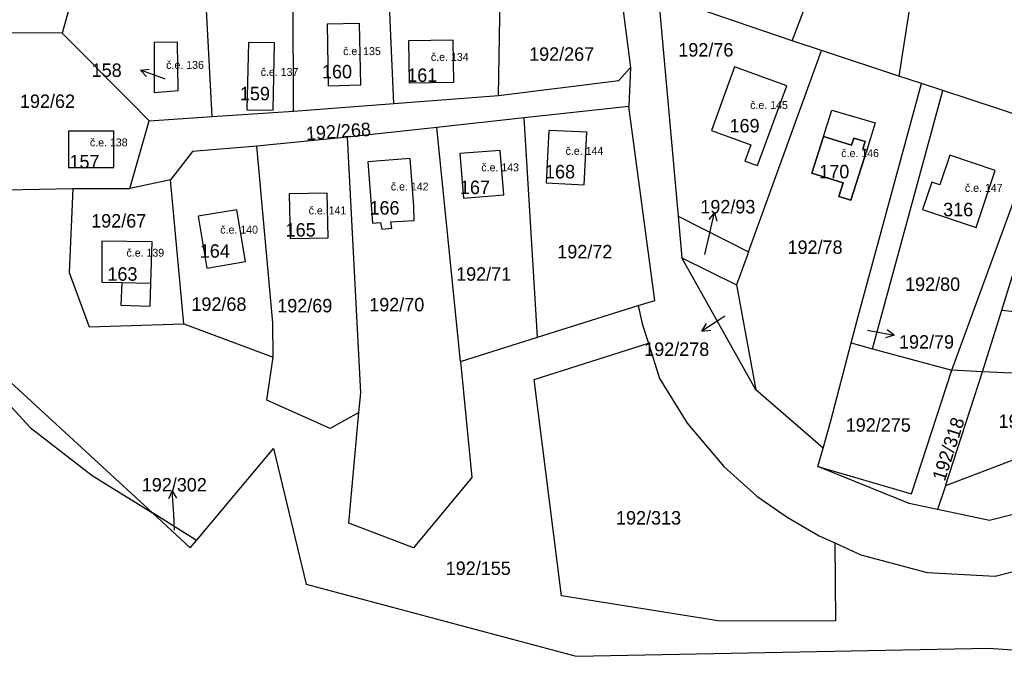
# Model space of a CAD drawing. Extents: x -887272 to -880188, y -1026687 to -1021896.
# Drawn here: x -882457.7 to -882333.3, y -1024320.7 to -1024238.2 of the extents above; entities that cross this region are included whole.
import ezdxf

# ---------------------------------------------------------------- set-up
doc = ezdxf.new("R2010")
doc.units = 0
for name, color, linetype in [('Definiční body', 7, 'Continuous'), ('Hranice parcel', 7, 'Continuous'), ('Parcelní čísla', 7, 'Continuous'), ('Polygon budovy', 7, 'Continuous'), ('Pop  PČ popisy', 7, 'Continuous'), ('Vnitřní kresba', 7, 'Continuous')]:
    doc.layers.add(name, color=color, linetype=linetype)

msp = doc.modelspace()

# ---------------------------------------------------------------- linework, layer by layer
at = {"layer": 'Hranice parcel'}
for p, q in [((-882410.38, -1024248.8), (-882411.4, -1024225.24)), ((-882397.17, -1024247.78), (-882396.78, -1024225.38)), ((-882382.84, -1024225.57), (-882380.49, -1024244.25)), ((-882423.04, -1024249.77), (-882423.15, -1024226.52)), ((-882433.35, -1024250.44), (-882434.56, -1024227.19)), ((-882360.05, -1024240.88), (-882376.96, -1024235.08)), ((-882376.96, -1024235.08), (-882374.46, -1024263.02)), ((-882452.28, -1024239.89), (-882460.64, -1024239.85)), ((-882356.35, -1024242.1), (-882360.05, -1024240.88)), ((-882365.56, -1024267.53), (-882356.35, -1024242.1)), ((-882346.59, -1024245.32), (-882356.35, -1024242.1)), ((-882380.49, -1024244.25), (-882380.71, -1024249.15)), ((-882343.72, -1024246.27), (-882346.59, -1024245.32)), ((-882341.03, -1024247.16), (-882343.72, -1024246.27)), ((-882410.38, -1024248.8), (-882397.17, -1024247.78)), ((-882349.89, -1024279.78), (-882341.03, -1024247.16)), ((-882328.48, -1024251.3), (-882341.03, -1024247.16)), ((-882423.04, -1024249.77), (-882410.38, -1024248.8)), ((-882380.71, -1024249.15), (-882393.92, -1024250.6)), ((-882441.28, -1024250.96), (-882433.35, -1024250.44)), ((-882433.35, -1024250.44), (-882423.04, -1024249.77)), ((-882393.92, -1024250.6), (-882404.93, -1024251.81)), ((-882392.22, -1024278.32), (-882393.92, -1024250.6)), ((-882443.73, -1024259.52), (-882441.28, -1024250.96)), ((-882404.93, -1024251.81), (-882416.23, -1024253.06)), ((-882401.95, -1024281.38), (-882404.93, -1024251.81)), ((-882339.9, -1024282.5), (-882328.48, -1024251.3)), ((-882416.23, -1024253.06), (-882427.71, -1024254.18)), ((-882438.6, -1024258.43), (-882443.73, -1024259.52)), ((-882436.92, -1024276.61), (-882438.6, -1024258.43)), ((-882450.92, -1024259.54), (-882443.73, -1024259.52)), ((-882374.46, -1024263.02), (-882365.56, -1024267.53)), ((-882374.46, -1024263.02), (-882373.99, -1024268.29)), ((-882434.02, -1024269.59), (-882429.14, -1024268.77)), ((-882373.99, -1024268.29), (-882367.08, -1024271.72)), ((-882364.65, -1024284.97), (-882373.99, -1024268.29)), ((-882367.08, -1024271.72), (-882364.65, -1024284.97)), ((-882392.22, -1024278.32), (-882379.5, -1024274.33)), ((-882379.5, -1024274.33), (-882379, -1024276.62)), ((-882335.99, -1024282.71), (-882333.57, -1024274.9)), ((-882333.57, -1024274.9), (-882314.06, -1024277.04)), ((-882436.92, -1024276.61), (-882425.64, -1024280.82)), ((-882379, -1024276.62), (-882378.22, -1024279.09)), ((-882401.95, -1024281.38), (-882392.22, -1024278.32)), ((-882352.62, -1024279.03), (-882349.89, -1024279.78)), ((-882349.89, -1024279.78), (-882339.9, -1024282.5)), ((-882340.7, -1024297.09), (-882335.99, -1024282.71)), ((-882335.99, -1024282.71), (-882339.9, -1024282.5)), ((-882305.94, -1024283.91), (-882335.99, -1024282.71)), ((-882305.94, -1024283.91), (-882340.7, -1024297.09)), ((-882356.14, -1024292.34), (-882364.65, -1024284.97)), ((-882435.31, -1024303.99), (-882425.59, -1024292.38)), ((-882356.8, -1024294.67), (-882356.14, -1024292.34)), ((-882340.7, -1024297.09), (-882341.68, -1024300.07)), ((-882435.31, -1024303.99), (-882440.89, -1024300.52))]:
    msp.add_line(p, q, dxfattribs=at)
for points in [[(-882425.59, -1024292.38), (-882421.44, -1024309.52), (-882387.34, -1024318.62), (-882335.2, -1024317.62), (-882324.6, -1024318.36), (-882301.38, -1024320.66), (-882228.26, -1024295.72), (-882166.04, -1024261.72), (-882132.4, -1024219.02), (-882083.16, -1024195.4)], [(-882346.41, -1024203.09), (-882344.31, -1024230.73), (-882346.59, -1024245.32)], [(-882360.05, -1024240.88), (-882355.97, -1024230.12), (-882356.96, -1024221.54)], [(-882434.56, -1024227.19), (-882450.17, -1024232.3), (-882452.28, -1024239.89)], [(-882440.89, -1024300.52), (-882464.08, -1024279.19), (-882474.4, -1024257.7), (-882487.23, -1024239.16)], [(-882487.23, -1024239.16), (-882478.4, -1024256.44), (-882466.55, -1024277.28), (-882463.36, -1024282.12), (-882456.33, -1024289.73), (-882448.49, -1024295.79), (-882440.89, -1024300.52)], [(-882418.81, -1024238.75), (-882418.66, -1024246.56), (-882414.56, -1024246.42), (-882414.71, -1024238.67), (-882418.81, -1024238.75)], [(-882460.64, -1024239.85), (-882459.44, -1024259.7), (-882450.92, -1024259.54)], [(-882441.28, -1024250.96), (-882443.66, -1024248.58), (-882452.28, -1024239.89)], [(-882408.51, -1024240.88), (-882408.43, -1024246.19), (-882402.82, -1024246.1), (-882402.9, -1024240.79), (-882408.51, -1024240.88)], [(-882440.66, -1024241.1), (-882440.68, -1024247.38), (-882437.62, -1024247.16), (-882437.7, -1024241.02), (-882440.66, -1024241.1)], [(-882428.97, -1024249.57), (-882425.65, -1024249.65), (-882425.44, -1024241.14), (-882428.76, -1024241.06), (-882428.97, -1024249.57)], [(-882397.17, -1024247.78), (-882381.94, -1024245.87), (-882380.49, -1024244.25)], [(-882360.75, -1024246.56), (-882367.33, -1024244.15), (-882370.24, -1024252.19), (-882365.28, -1024254.01), (-882366.02, -1024256.06), (-882364.42, -1024256.61), (-882360.75, -1024246.56)], [(-882352.62, -1024279.03), (-882351.55, -1024275.07), (-882343.72, -1024246.27)], [(-882379.5, -1024274.33), (-882377.41, -1024273.67), (-882380.71, -1024249.15)], [(-882354.14, -1024260.55), (-882353.6, -1024258.83), (-882357.56, -1024257.58), (-882356.1, -1024252.96), (-882355.05, -1024249.64), (-882349.56, -1024251.25), (-882350.64, -1024254.68), (-882352.64, -1024261.02), (-882354.14, -1024260.55)], [(-882451.48, -1024252.28), (-882451.48, -1024256.88), (-882445.78, -1024256.88), (-882445.78, -1024252.28), (-882451.48, -1024252.28)], [(-882414.79, -1024287.85), (-882414.56, -1024285.34), (-882416.23, -1024253.06)], [(-882391.15, -1024258.82), (-882386.34, -1024259.06), (-882386.01, -1024252.42), (-882390.82, -1024252.18), (-882391.15, -1024258.82)], [(-882427.71, -1024254.18), (-882435.8, -1024254.84), (-882438.6, -1024258.43)], [(-882425.64, -1024280.82), (-882425.69, -1024276.49), (-882427.71, -1024254.18)], [(-882396.94, -1024254.71), (-882402.03, -1024255.11), (-882401.59, -1024260.74), (-882396.5, -1024260.34), (-882396.94, -1024254.71)], [(-882336.79, -1024264.46), (-882334.39, -1024257.24), (-882340.13, -1024255.33), (-882341.38, -1024259.08), (-882342.43, -1024258.74), (-882343.58, -1024262.2), (-882336.79, -1024264.46)], [(-882333.57, -1024274.9), (-882328.36, -1024258.07), (-882318.06, -1024254.51)], [(-882411.9, -1024264.66), (-882410.63, -1024264.56), (-882410.75, -1024263.76), (-882407.81, -1024263.55), (-882407.87, -1024261.75), (-882408.3, -1024255.75), (-882413.68, -1024256.16), (-882413.22, -1024262.15), (-882413.07, -1024263.89), (-882412.07, -1024263.84), (-882411.9, -1024264.66)], [(-882450.92, -1024259.54), (-882451.4, -1024270.13), (-882448.89, -1024276.99), (-882436.92, -1024276.61)], [(-882418.79, -1024260.13), (-882423.59, -1024260.21), (-882423.5, -1024265.86), (-882418.68, -1024265.78), (-882418.79, -1024260.13)], [(-882429.14, -1024268.77), (-882430.24, -1024262.21), (-882435.12, -1024263.03), (-882434.02, -1024269.59)], [(-882441.17, -1024274.38), (-882441.08, -1024271.49), (-882440.92, -1024266.26), (-882447.28, -1024266.19), (-882447.29, -1024271.35), (-882444.75, -1024271.41), (-882444.86, -1024274.27), (-882441.17, -1024274.38)], [(-882365.56, -1024267.53), (-882365.7, -1024267.92), (-882367.08, -1024271.72)], [(-882354.68, -1024304.32), (-882354.6, -1024314.14), (-882369.14, -1024314.18), (-882389.2, -1024310.99), (-882392.65, -1024283.66), (-882378.22, -1024279.09)], [(-882378.22, -1024279.09), (-882376.81, -1024283.53), (-882373.32, -1024289.17), (-882368.7, -1024294.66), (-882364.52, -1024298.39), (-882360.7, -1024301.04), (-882356.66, -1024303.42), (-882354.68, -1024304.32)], [(-882356.14, -1024292.34), (-882355.16, -1024288.88), (-882352.62, -1024279.03)], [(-882414.79, -1024287.85), (-882418.44, -1024289.85), (-882426.45, -1024286.28), (-882425.64, -1024280.82)], [(-882401.95, -1024281.38), (-882400.53, -1024296.03), (-882407.89, -1024304.93), (-882416.08, -1024301.82), (-882414.79, -1024287.85)], [(-882356.8, -1024294.67), (-882344.99, -1024298.1), (-882339.9, -1024282.5)], [(-882341.68, -1024300.07), (-882345.28, -1024299.31), (-882356.8, -1024294.67)], [(-882354.68, -1024304.32), (-882351.37, -1024305.83), (-882343, -1024308.06), (-882334.42, -1024308.5), (-882328.14, -1024306.91), (-882327.09, -1024306.65), (-882328.81, -1024299.87)], [(-882328.81, -1024299.87), (-882335.11, -1024301.46), (-882341.68, -1024300.07)], [(-882440.89, -1024300.52), (-882436.1, -1024304.93), (-882435.31, -1024303.99)]]:
    msp.add_lwpolyline(points, dxfattribs=at)
at = {"layer": 'Polygon budovy'}
for points in [[(-882414.56, -1024246.42), (-882414.71, -1024238.67), (-882418.81, -1024238.75), (-882418.66, -1024246.56)], [(-882408.51, -1024240.88), (-882408.43, -1024246.19), (-882402.82, -1024246.1), (-882402.9, -1024240.79)], [(-882437.62, -1024247.16), (-882437.7, -1024241.02), (-882440.66, -1024241.1), (-882440.68, -1024247.38)], [(-882428.76, -1024241.06), (-882428.97, -1024249.57), (-882425.65, -1024249.65), (-882425.44, -1024241.14)], [(-882367.33, -1024244.15), (-882370.24, -1024252.19), (-882365.28, -1024254.01), (-882366.02, -1024256.06), (-882364.42, -1024256.61), (-882360.75, -1024246.56)], [(-882445.78, -1024256.88), (-882445.78, -1024252.28), (-882451.48, -1024252.28), (-882451.48, -1024256.88)], [(-882386.01, -1024252.42), (-882390.82, -1024252.18), (-882391.15, -1024258.82), (-882386.34, -1024259.06)], [(-882356.1, -1024252.96), (-882357.56, -1024257.58), (-882353.6, -1024258.83), (-882354.14, -1024260.55), (-882352.64, -1024261.02), (-882350.64, -1024254.68), (-882351.12, -1024254.53), (-882350.83, -1024253.6), (-882352.28, -1024253.15), (-882352.57, -1024254.07)], [(-882401.59, -1024260.74), (-882396.5, -1024260.34), (-882396.94, -1024254.71), (-882402.03, -1024255.11)], [(-882340.13, -1024255.33), (-882341.38, -1024259.08), (-882342.43, -1024258.74), (-882343.58, -1024262.2), (-882336.79, -1024264.46), (-882334.39, -1024257.24)], [(-882410.75, -1024263.76), (-882407.81, -1024263.55), (-882407.87, -1024261.75), (-882408.3, -1024255.75), (-882413.68, -1024256.16), (-882413.22, -1024262.15), (-882413.07, -1024263.89), (-882412.07, -1024263.84), (-882411.9, -1024264.66), (-882410.63, -1024264.56)], [(-882423.5, -1024265.86), (-882418.68, -1024265.78), (-882418.79, -1024260.13), (-882423.59, -1024260.21)], [(-882434.02, -1024269.59), (-882429.14, -1024268.77), (-882430.24, -1024262.21), (-882435.12, -1024263.03)], [(-882444.75, -1024271.41), (-882441.08, -1024271.49), (-882440.92, -1024266.26), (-882447.28, -1024266.19), (-882447.29, -1024271.35)]]:
    msp.add_lwpolyline(points, close=True, dxfattribs=at)
at = {"layer": 'Pop  PČ popisy'}
for p, q in [((-882442.4, -1024244.57), (-882441.29, -1024244.45)), ((-882439.58, -1024245.6), (-882442.4, -1024244.57)), ((-882442.4, -1024244.57), (-882441.63, -1024245.39)), ((-882439.26, -1024245.72), (-882439.58, -1024245.6)), ((-882369.85, -1024262.58), (-882370.57, -1024263.44)), ((-882370.53, -1024265.5), (-882369.85, -1024262.58)), ((-882369.85, -1024262.58), (-882369.59, -1024263.66)), ((-882371.09, -1024267.88), (-882370.53, -1024265.5)), ((-882368.94, -1024275.92), (-882371.46, -1024277.55)), ((-882371.46, -1024277.55), (-882370.89, -1024276.59)), ((-882368.56, -1024275.67), (-882368.94, -1024275.92)), ((-882371.46, -1024277.55), (-882370.34, -1024277.43)), ((-882350.56, -1024277.42), (-882350.12, -1024277.51)), ((-882350.12, -1024277.51), (-882347.17, -1024278.08)), ((-882347.17, -1024278.08), (-882348.25, -1024278.38)), ((-882347.17, -1024278.08), (-882348.06, -1024277.4)), ((-882438.41, -1024297.71), (-882438.84, -1024298.74)), ((-882438.2, -1024300.7), (-882438.41, -1024297.71)), ((-882438.41, -1024297.71), (-882437.84, -1024298.67)), ((-882438.08, -1024302.69), (-882438.2, -1024300.7))]:
    msp.add_line(p, q, dxfattribs=at)
at = {"layer": 'Vnitřní kresba'}
for p, q in [((-882356.1, -1024252.96), (-882352.57, -1024254.07)), ((-882352.57, -1024254.07), (-882352.28, -1024253.15)), ((-882352.28, -1024253.15), (-882350.83, -1024253.6)), ((-882350.83, -1024253.6), (-882351.12, -1024254.53)), ((-882351.12, -1024254.53), (-882350.64, -1024254.68)), ((-882444.75, -1024271.41), (-882441.08, -1024271.49))]:
    msp.add_line(p, q, dxfattribs=at)

# ---------------------------------------------------------------- texts
at = {"layer": 'Definiční body'}
for s, p in [('č.e. 135', (-882416.79, -1024242.67)), ('č.e. 134', (-882405.7, -1024243.41)), ('č.e. 136', (-882439.14, -1024244.41)), ('č.e. 137', (-882427.2, -1024245.3)), ('č.e. 145', (-882365.36, -1024249.48)), ('č.e. 138', (-882448.78, -1024254.2)), ('č.e. 144', (-882388.68, -1024255.28)), ('č.e. 146', (-882353.85, -1024255.56)), ('č.e. 143', (-882399.33, -1024257.36)), ('č.e. 142', (-882410.76, -1024259.78)), ('č.e. 147', (-882338.23, -1024259.95)), ('č.e. 141', (-882421.15, -1024262.8)), ('č.e. 140', (-882432.31, -1024265.23)), ('č.e. 139', (-882444.16, -1024268.14))]:
    msp.add_text(s, height=1, dxfattribs=at).set_placement(p)
at = {"layer": 'Parcelní čísla'}
for s, p in [('192/267', (-882393.29, -1024243.39)), ('192/76', (-882374.44, -1024242.86)), ('158', (-882448.56, -1024245.43)), ('160', (-882419.46, -1024245.61)), ('161', (-882408.69, -1024246.06)), ('159', (-882429.83, -1024248.38)), ('192/62', (-882457.62, -1024249.35)), ('169', (-882367.97, -1024252.44)), ('157', (-882451.36, -1024256.98)), ('168', (-882391.28, -1024258.25)), ('170', (-882356.63, -1024258.24)), ('167', (-882402.03, -1024260.23)), ('166', (-882413.46, -1024262.82)), ('192/93', (-882371.66, -1024262.68)), ('316', (-882340.98, -1024263.03)), ('192/67', (-882448.62, -1024264.46)), ('165', (-882424.05, -1024265.6)), ('164', (-882434.9, -1024268.27)), ('192/72', (-882389.73, -1024268.36)), ('192/78', (-882360.64, -1024267.79)), ('192/71', (-882402.51, -1024271.18)), ('163', (-882446.57, -1024271.18)), ('192/80', (-882345.79, -1024272.47)), ('192/68', (-882435.96, -1024274.99)), ('192/69', (-882425.11, -1024275.18)), ('192/70', (-882413.49, -1024275.05)), ('192/79', (-882346.56, -1024279.76)), ('192/278', (-882378.75, -1024280.68)), ('192/291', (-882333.98, -1024289.78)), ('192/275', (-882353.29, -1024290.26)), ('192/302', (-882442.23, -1024297.81)), ('192/313', (-882382.31, -1024301.99)), ('192/155', (-882403.83, -1024308.36))]:
    msp.add_text(s, height=1.7, dxfattribs=at).set_placement(p)
for s, rotation, p in [('192/268', 4, (-882421.43, -1024253.44)), ('192/318', 72, (-882340.78, -1024296.61))]:
    msp.add_text(s, height=1.7, rotation=rotation, dxfattribs=at).set_placement(p)

doc.saveas('drawing.dxf')
